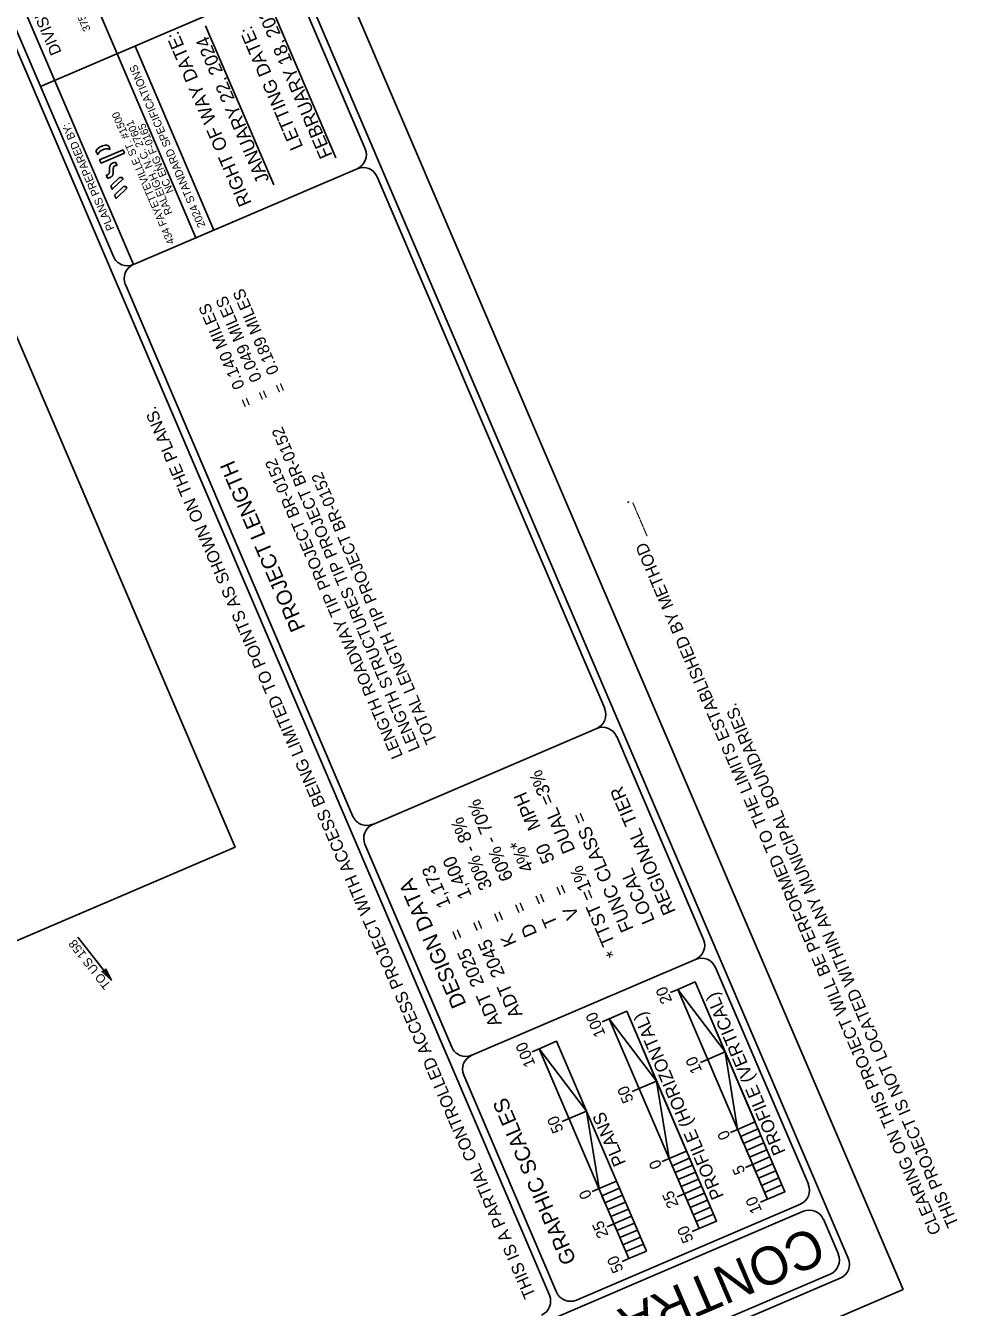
# Model space of a CAD drawing. Extents: x 1550250 to 1553210, y 808906 to 812497.
# Drawn here: x 1552154 to 1553210, y 809643 to 811095 of the extents above; entities that cross this region are included whole.
import ezdxf

# ---------------------------------------------------------------- set-up
doc = ezdxf.new("R2010")
doc.units = 0
for name, color, linetype in [('Default', 7, 'Continuous'), ('Prop DSN Text', 7, 'Continuous'), ('Prop Terminator Cell', 7, 'Continuous'), ('Scratch_Level_0', 7, 'Continuous'), ('Sheet Data Field CELL', 7, 'Continuous'), ('Sheet Title CELL', 7, 'Continuous'), ('Sheet_Data_Field_CELL', 7, 'Continuous'), ('Sheet_Plan_CELL', 7, 'Continuous'), ('Sheet_Title_CELL', 7, 'Continuous')]:
    doc.layers.add(name, color=color, linetype=linetype)

msp = doc.modelspace()

# ---------------------------------------------------------------- linework, layer by layer
at = {"layer": 'Default'}
for p, q in [((1552237.8, 810943), (1552264.3, 810954.3)), ((1552265.9, 810950.6), (1552239.4, 810939.3)), ((1552264.3, 810954.3), (1552265.9, 810950.6)), ((1552239.4, 810939.3), (1552237.8, 810943)), ((1552250.3, 810913.5), (1552260.4, 810922.9)), ((1552264.1, 810921), (1552252, 810909.6)), ((1552260.4, 810922.9), (1552263.2, 810923.1)), ((1552263.2, 810923.1), (1552264.1, 810921)), ((1552252, 810909.6), (1552250.3, 810913.5)), ((1552254.8, 810903.1), (1552264.8, 810912.6)), ((1552256.4, 810899.3), (1552254.8, 810903.1)), ((1552268.5, 810910.7), (1552256.4, 810899.3)), ((1552264.8, 810912.6), (1552267.6, 810912.7)), ((1552267.6, 810912.7), (1552268.5, 810910.7))]:
    msp.add_line(p, q, dxfattribs=at)
for points in [[(1552264.3, 810954.3), (1552237.8, 810943), (1552239.4, 810939.3), (1552265.9, 810950.6), (1552264.3, 810954.3)], [(1552250.3, 810913.5), (1552252, 810909.6), (1552264.1, 810921), (1552263.2, 810923.1), (1552260.4, 810922.9), (1552250.3, 810913.5)], [(1552254.8, 810903.1), (1552256.4, 810899.3), (1552268.5, 810910.7), (1552267.6, 810912.7), (1552264.8, 810912.6), (1552254.8, 810903.1)]]:
    msp.add_lwpolyline(points, dxfattribs=at)
for points in [[(1552241.4, 810954.3), (1552238.4, 810953), (1552236.4, 810950.8), (1552235.4, 810948.7), (1552235.4, 810948.7), (1552233.6, 810952.9), (1552233.6, 810952.9), (1552234.7, 810955), (1552237.1, 810957), (1552239.8, 810958.2), (1552239.8, 810958.2), (1552239.8, 810958.2), (1552239.8, 810958.2), (1552242.5, 810959.3), (1552245.7, 810959.7), (1552247.9, 810959), (1552247.9, 810959), (1552249.7, 810954.8), (1552249.7, 810954.8), (1552247.5, 810955.5), (1552244.5, 810955.6), (1552241.5, 810954.3), (1552241.5, 810954.3), (1552241.4, 810954.3), (1552241.4, 810954.3)], [(1552241.4, 810954.3), (1552241.4, 810954.3), (1552241.5, 810954.3), (1552241.5, 810954.3), (1552244.5, 810955.6), (1552247.5, 810955.5), (1552249.7, 810954.8), (1552249.7, 810954.8), (1552247.9, 810959), (1552247.9, 810959), (1552245.7, 810959.7), (1552242.5, 810959.3), (1552239.8, 810958.2), (1552239.8, 810958.2), (1552239.8, 810958.2), (1552239.8, 810958.2), (1552237.1, 810957), (1552234.7, 810955), (1552233.6, 810952.9), (1552233.6, 810952.9), (1552235.4, 810948.7), (1552235.4, 810948.7), (1552236.4, 810950.8), (1552238.4, 810953), (1552241.4, 810954.3)], [(1552248.9, 810922.7), (1552248.2, 810922.4), (1552247.4, 810922.3), (1552246.6, 810922.3), (1552246.6, 810922.3), (1552245.2, 810925.7), (1552245.2, 810925.7), (1552245.8, 810925.6), (1552246.8, 810925.7), (1552247.6, 810926.4), (1552248.3, 810927.1), (1552248.7, 810927.9), (1552248.8, 810928.8), (1552249, 810929.9), (1552248.9, 810931), (1552248.9, 810932.2), (1552249, 810933.3), (1552249, 810934.5), (1552249.4, 810935.6), (1552249.9, 810937.2), (1552250.8, 810938.4), (1552252.3, 810939.2), (1552252.5, 810939.3), (1552252.7, 810939.4), (1552252.9, 810939.5), (1552253.9, 810939.9), (1552254.9, 810940.1), (1552256, 810940.1), (1552256, 810940.1), (1552257.5, 810936.6), (1552257.5, 810936.6), (1552256.7, 810936.7), (1552255.8, 810936.6), (1552255.1, 810936.3), (1552253.4, 810935.4), (1552253.3, 810932.7), (1552253.3, 810930.5), (1552253.3, 810930.2), (1552253.3, 810929.9), (1552253.3, 810929.6), (1552253.2, 810928.6), (1552253.1, 810927.6), (1552252.9, 810926.7), (1552252.6, 810925.7), (1552252.2, 810924.9), (1552251.5, 810924.2), (1552250.8, 810923.6), (1552250, 810923.1), (1552249.2, 810922.8), (1552249.1, 810922.8), (1552249, 810922.7), (1552248.9, 810922.7)], [(1552248.9, 810922.7), (1552249, 810922.7), (1552249.1, 810922.8), (1552249.2, 810922.8), (1552250, 810923.1), (1552250.8, 810923.6), (1552251.5, 810924.2), (1552252.2, 810924.9), (1552252.6, 810925.7), (1552252.9, 810926.7), (1552253.1, 810927.6), (1552253.2, 810928.6), (1552253.3, 810929.6), (1552253.3, 810929.9), (1552253.3, 810930.2), (1552253.3, 810930.5), (1552253.3, 810932.7), (1552253.4, 810935.4), (1552255.1, 810936.3), (1552255.8, 810936.6), (1552256.7, 810936.7), (1552257.5, 810936.6), (1552257.5, 810936.6), (1552256, 810940.1), (1552256, 810940.1), (1552254.9, 810940.1), (1552253.9, 810939.9), (1552252.9, 810939.5), (1552252.7, 810939.4), (1552252.5, 810939.3), (1552252.3, 810939.2), (1552250.8, 810938.4), (1552249.9, 810937.2), (1552249.4, 810935.6), (1552249, 810934.5), (1552249, 810933.3), (1552248.9, 810932.2), (1552248.9, 810931), (1552249, 810929.9), (1552248.8, 810928.8), (1552248.7, 810927.9), (1552248.3, 810927.1), (1552247.6, 810926.4), (1552246.8, 810925.7), (1552245.8, 810925.6), (1552245.2, 810925.7), (1552245.2, 810925.7), (1552246.6, 810922.3), (1552246.6, 810922.3), (1552247.4, 810922.3), (1552248.2, 810922.4), (1552248.9, 810922.7)]]:
    msp.add_open_spline(points, degree=3, dxfattribs=at)
at = {"layer": 'Prop DSN Text'}
msp.add_line((1552251.4, 810013.4), (1552213, 810062), dxfattribs=at)
at = {"layer": 'Prop Terminator Cell'}
msp.add_lwpolyline([(1552244.4, 810026.2), (1552251.4, 810013.4), (1552240.4, 810023.1), (1552243.5, 810023.3)], close=True, dxfattribs=at)
at = {"layer": 'Scratch_Level_0'}
for q in [(1551994.4, 812358.6), (1551404, 808916)]:
    msp.add_line((1553148.4, 809662.7), q, dxfattribs=at)
at = {"layer": 'Sheet Title CELL'}
for p, q in [((1552140, 811338.3), (1552347, 810854.7)), ((1552069, 811308), (1552276.1, 810824.3)), ((1552170.9, 811026.1), (1552456.3, 811148.3)), ((1552428.4, 811125.8), (1552505.6, 810945.4)), ((1552357.9, 811094.9), (1552435.1, 810914.5)), ((1552278, 811071.9), (1552367.3, 810863.3)), ((1552303.7, 811011.8), (1552303.7, 811011.8))]:
    msp.add_line(p, q, dxfattribs=at)
at = {"layer": 'Sheet_Data_Field_CELL'}
msp.add_line((1553148.4, 809662.7), (1553148.4, 809662.7), dxfattribs=at)
at = {"layer": 'Sheet_Plan_CELL'}
msp.add_lwpolyline([(1551190.2, 811336.1), (1551800.2, 809911.1), (1552391.4, 810164.1), (1551781.4, 811589.2)], close=True, dxfattribs=at)
at = {"layer": 'Sheet_Title_CELL'}
for p, q in [((1553086.3, 809698.2), (1551984, 812273.4)), ((1552747.8, 809656.4), (1551686.1, 812136.6)), ((1552253.4, 810833.3), (1552059.9, 811285.3)), ((1552276, 810824.3), (1552529.7, 810932.9)), ((1552276, 810824.3), (1552529.7, 810932.9)), ((1552524.9, 810199), (1552267, 810801.6)), ((1552547.5, 810189.9), (1552801.3, 810298.5)), ((1552636.9, 809937.3), (1552538.5, 810167.3)), ((1552659.5, 809928.3), (1552913.3, 810036.9)), ((1552893, 810002.8), (1552885, 809999.5)), ((1552912.8, 810011.3), (1552893, 810002.8)), ((1552893, 810002.8), (1552994.8, 809765)), ((1553014.6, 809773.5), (1552912.8, 810011.3)), ((1552835.2, 809978.1), (1552815.4, 809969.6)), ((1552937, 809740.3), (1552835.2, 809978.1)), ((1552815.4, 809969.6), (1552807.5, 809966.3)), ((1552815.4, 809969.6), (1552917.2, 809731.8)), ((1552755.8, 809944.1), (1552735.9, 809935.6)), ((1552857.6, 809706.3), (1552755.8, 809944.1)), ((1552735.9, 809935.6), (1552728, 809932.2)), ((1552735.9, 809935.6), (1552837.8, 809697.8)), ((1552926.9, 809923.6), (1552946.7, 809932)), ((1552926.9, 809923.6), (1552919, 809920.2)), ((1552755.7, 809659.8), (1552650.5, 809905.6)), ((1552849.3, 809890.4), (1552841.4, 809887)), ((1552849.3, 809890.4), (1552869.1, 809898.8)), ((1552769.9, 809856.4), (1552789.7, 809864.8)), ((1552769.9, 809856.4), (1552762, 809853)), ((1552960.9, 809844.3), (1552952.9, 809840.9)), ((1552971, 809820.5), (1552990.8, 809829)), ((1552883.3, 809811.1), (1552875.4, 809807.7)), ((1552977.8, 809804.6), (1552969.9, 809801.2)), ((1552893.4, 809787.3), (1552913.3, 809795.8)), ((1552803.9, 809777.1), (1552795.9, 809773.7)), ((1552900.3, 809771.4), (1552892.3, 809768)), ((1552994.8, 809765), (1553014.6, 809773.5)), ((1553032.1, 809759.4), (1552778.3, 809650.8)), ((1552814, 809753.3), (1552833.8, 809761.8)), ((1552994.8, 809765), (1552986.9, 809761.6)), ((1552986.9, 809761.6), (1552986.9, 809761.6)), ((1552994.8, 809765), (1552994.8, 809765)), ((1553035.5, 809751.4), (1551417.9, 809059)), ((1552820.8, 809737.4), (1552812.9, 809734)), ((1552917.2, 809731.8), (1552909.3, 809728.4)), ((1552909.3, 809728.4), (1552909.3, 809728.4)), ((1552917.2, 809731.8), (1552937, 809740.3)), ((1552917.2, 809731.8), (1552917.2, 809731.8)), ((1552837.8, 809697.8), (1552829.9, 809694.4)), ((1552837.8, 809697.8), (1552857.6, 809706.3)), ((1552837.8, 809697.8), (1552837.8, 809697.8)), ((1552829.9, 809694.4), (1552829.9, 809694.4))]:
    msp.add_line(p, q, dxfattribs=at)
for points in [[(1552538.8, 810955.5), (1552345.4, 811407.5)], [(1552810.4, 810321.2), (1552552.4, 810923.8)], [(1552922.3, 810059.5), (1552823.9, 810289.5)], [(1553041.2, 809782), (1552935.9, 810027.8)], [(1553075.1, 809702.7), (1553058.1, 809742.4)], [(1551443.9, 808976.4), (1553077.3, 809675.5)], [(1551443.9, 808976.4), (1553077.3, 809675.5)], [(1551448.5, 808987.7), (1553066, 809680.1)]]:
    msp.add_lwpolyline(points, dxfattribs=at)
for points in [[(1552893, 810002.8), (1552946.7, 809932), (1552912.8, 810011.3)], [(1552815.4, 809969.6), (1552869.1, 809898.8), (1552835.2, 809978.1)], [(1552735.9, 809935.6), (1552789.7, 809864.8), (1552755.8, 809944.1)], [(1552960.9, 809844.3), (1552946.7, 809932), (1552980.7, 809852.8)], [(1552883.3, 809811.1), (1552869.1, 809898.8), (1552903.1, 809819.6)], [(1552803.9, 809777.1), (1552789.7, 809864.8), (1552823.7, 809785.6)], [(1552967.6, 809828.4), (1552964.2, 809836.3), (1552984.1, 809844.8), (1552987.4, 809836.9)], [(1552974.4, 809812.6), (1552971, 809820.5), (1552990.8, 809829), (1552994.2, 809821)], [(1552981.2, 809796.7), (1552977.8, 809804.6), (1552997.6, 809813.1), (1553001, 809805.2)], [(1552890.1, 809795.2), (1552886.7, 809803.1), (1552906.5, 809811.6), (1552909.9, 809803.7)], [(1552896.9, 809779.4), (1552893.4, 809787.3), (1552913.3, 809795.8), (1552916.7, 809787.8)], [(1552988, 809780.8), (1552984.6, 809788.8), (1553004.4, 809797.3), (1553007.8, 809789.3)], [(1552810.6, 809761.2), (1552807.2, 809769.1), (1552827.1, 809777.6), (1552830.4, 809769.7)], [(1552903.7, 809763.5), (1552900.3, 809771.4), (1552920.1, 809779.9), (1552923.5, 809772)], [(1552994.8, 809765), (1552991.4, 809772.9), (1553011.2, 809781.4), (1553014.6, 809773.5)], [(1552817.4, 809745.4), (1552814, 809753.3), (1552833.8, 809761.8), (1552837.2, 809753.8)], [(1552910.4, 809747.6), (1552907, 809755.6), (1552926.9, 809764.1), (1552930.3, 809756.1)], [(1552824.2, 809729.5), (1552820.8, 809737.4), (1552840.6, 809745.9), (1552844, 809738)], [(1552917.2, 809731.8), (1552913.8, 809739.7), (1552933.6, 809748.2), (1552937, 809740.3)], [(1552831, 809713.6), (1552827.6, 809721.6), (1552847.4, 809730.1), (1552850.8, 809722.1)], [(1552837.8, 809697.8), (1552834.4, 809705.7), (1552854.2, 809714.2), (1552857.6, 809706.3)]]:
    msp.add_lwpolyline(points, close=True, dxfattribs=at)
for centre, start, end in [((1552522.9, 810948.7), 293.1736, 23.1736), ((1552536.5, 810917), 23.1736, 113.1736), ((1552269.2, 810840.1), 203.1736, 293.1736), ((1552282.7, 810808.4), 113.1736, 203.1736), ((1552794.4, 810314.4), 293.1736, 23.1736), ((1552808, 810282.7), 23.1736, 113.1736), ((1552540.7, 810205.8), 203.1736, 293.1736), ((1552554.3, 810174), 113.1736, 203.1736), ((1552906.4, 810052.7), 293.1736, 23.1736), ((1552920, 810021), 23.1736, 113.1736), ((1552652.7, 809944.1), 203.1736, 293.1736), ((1552666.3, 809912.4), 113.1736, 203.1736), ((1553025.2, 809775.2), 293.1736, 23.1736), ((1553042.2, 809735.6), 23.1736, 113.1736), ((1553059.1, 809695.9), 293.1736, 23.1736), ((1553070.5, 809691.4), 293.1736, 23.1736), ((1552731.8, 809649.6), 293.1736, 23.1736), ((1552771.5, 809666.6), 203.1736, 293.1736)]:
    msp.add_arc(centre, 17.2, start, end, dxfattribs=at)

# ---------------------------------------------------------------- texts
at = {"layer": 'Prop DSN Text'}
msp.add_text('TO US 158', height=10, rotation=128.2468, dxfattribs=at).set_placement((1552251, 810007.9))
at = {"layer": 'Sheet Data Field CELL'}
for s, height, rotation, p in [('FEBRUARY 18, 2025', 15.094, 113.1759, (1552502, 810948.3)), ('JANUARY 22, 2024', 15.094, 113.1759, (1552430.4, 810920.4)), ('0.049 MILES', 13.417, 113.1736, (1552422, 810694.6)), ('0.189 MILES', 13.417, 113.1736, (1552441.4, 810702.9)), ('0.140 MILES', 13.417, 113.1736, (1552402.6, 810686.3)), ('=', 13.4, 113.1736, (1552450.1, 810682.4)), ('=', 13.4, 113.1736, (1552411.4, 810665.8)), ('=', 13.4, 113.1736, (1552430.8, 810674.1)), ('THIS IS A PARTIAL CONTROLLED ACCESS PROJECT WITH ACCESS BEING LIMITED TO POINTS AS SHOWN ON THE PLANS.', 13.8, 113.1736, (1552732.4, 809656.2)), ('LENGTH STRUCTURES TIP PROJECT BR-0152', 13.417, 113.1736, (1552601.2, 810275.9)), ('LENGTH ROADWAY TIP PROJECT BR-0152', 13.417, 113.1736, (1552581.8, 810267.6)), ('TOTAL LENGTH TIP PROJECT BR-0152', 13.417, 113.1736, (1552620.6, 810284.2)), ('CLEARING ON THIS PROJECT WILL BE PERFORMED TO THE LIMITS ESTABLISHED BY METHOD ____.', 13.8, 113.1736, (1553192.1, 809728.3)), ('THIS PROJECT IS NOT LOCATED WITHIN ANY MUNICIPAL BOUNDARIES.', 13.8, 113.1736, (1553211.9, 809736.7))]:
    msp.add_text(s, height=height, rotation=rotation, dxfattribs=at).set_placement(p)
at = {"layer": 'Sheet Title CELL'}
for s, height, rotation, p in [('DIVISION OF HIGHWAYS', 12.938, 113.1759, (1552194.9, 811064.9)), ('375 SILAS CREEK PARKWAY', 8.625, 113.1759, (1552227.8, 811090.7)), ('LETTING DATE:', 15.093, 113.1736, (1552468.7, 810957.8)), ('RIGHT OF WAY DATE: ', 15.093, 113.1736, (1552410.3, 810894)), ('2024 STANDARD SPECIFICATIONS', 8.97, 113.1736, (1552357.9, 810868.4)), ('434 FAYETTEVILLE ST. #1500', 8.625, 113.1759, (1552323, 810849.2)), ('PLANS PREPARED BY:', 8.97, 113.1759, (1552254.7, 810865.1)), ('RALEIGH, N.C. 27601', 8.625, 113.1759, (1552320.6, 810882.7)), ('NC ENG F-0165', 8.625, 113.1759, (1552321.9, 810907.3))]:
    msp.add_text(s, height=height, rotation=rotation, dxfattribs=at).set_placement(p)
at = {"layer": 'Sheet_Data_Field_CELL'}
for s, height, p in [('DUAL =3%', 15.09, (1552777.3, 810160.8)), ('MPH', 15.09, (1552738.2, 810186.9)), ('REGIONAL TIER', 15.094, (1552891, 810091.1)), ('60% - 70%', 15.09, (1552706.9, 810129.3)), ('30% - 8%', 15.09, (1552683.3, 810119.2)), ('FUNC CLASS =', 15.094, (1552843.4, 810071.6)), ('4%*', 15.09, (1552730.4, 810139.3)), ('50', 15.09, (1552754, 810149.4)), ('1,400', 15.09, (1552659.8, 810109.1)), ('1,173', 15.09, (1552636, 810098.9)), ('* TTST =1%', 15.09, (1552827.5, 810043.3)), ('LOCAL', 15.09, (1552867.4, 810080.9)), ('=', 15.1, (1552769.6, 810112.9)), ('=', 15.1, (1552745.8, 810102.8)), ('=', 15.1, (1552698.9, 810082.7)), ('=', 15.1, (1552722.7, 810092.8)), ('V', 15.1, (1552781.3, 810086.1)), ('=', 15.1, (1552675.3, 810072.6)), ('D', 15.1, (1552734, 810066)), ('T', 15.1, (1552757.2, 810077.1)), ('=', 15.1, (1552651.5, 810062.4)), ('K', 15.1, (1552710.6, 810055.2)), ('2025', 15.09, (1552674, 810009.7)), ('2045', 15.09, (1552697.5, 810020.1)), ('ADT', 15.09, (1552717.3, 809974.3)), ('20', 12.94, (1552887, 809989.8)), ('ADT', 15.09, (1552693.7, 809964.2)), ('100', 12.94, (1552811.4, 809952)), ('100', 12.94, (1552732, 809918)), ('10', 12.94, (1552920.9, 809910.6)), ('50', 12.94, (1552843.4, 809877.3)), ('50', 12.94, (1552763.9, 809843.3)), ('5', 12.9, (1552969.9, 809796.2)), ('25', 12.94, (1552894.3, 809758.3)), ('10', 12.94, (1552988.8, 809752)), ('25', 12.94, (1552814.9, 809724.3)), ('50', 12.94, (1552911.3, 809718.8)), ('50', 12.94, (1552831.8, 809684.8))]:
    msp.add_text(s, height=height, rotation=113.1736, dxfattribs=at).set_placement(p)
at = {"layer": 'Sheet_Title_CELL'}
for s, height, rotation, p in [('PROJECT LENGTH', 17.249, 113.1736, (1552471.2, 810412.7)), ('DESIGN DATA', 17.249, 113.1736, (1552653.8, 809986.2)), ('PROFILE (VERTICAL)', 14.662, 113.1736, (1553015.6, 809818.8)), ('PROFILE (HORIZONTAL)', 14.662, 113.1736, (1552945.7, 809768.5)), ('GRAPHIC SCALES', 17.249, 113.1736, (1552778.4, 809695.4)), ('PLANS', 14.66, 113.1736, (1552834.6, 809806.2)), ('0', 12.9, 113.1736, (1552953, 809835.7)), ('0', 12.9, 113.1736, (1552875.4, 809802.5)), ('0', 12.9, 113.1736, (1552796, 809768.5)), ('CONTRACT:', 43.12, 203.1736, (1553047.2, 809735.1))]:
    msp.add_text(s, height=height, rotation=rotation, dxfattribs=at).set_placement(p)

doc.saveas('drawing.dxf')
